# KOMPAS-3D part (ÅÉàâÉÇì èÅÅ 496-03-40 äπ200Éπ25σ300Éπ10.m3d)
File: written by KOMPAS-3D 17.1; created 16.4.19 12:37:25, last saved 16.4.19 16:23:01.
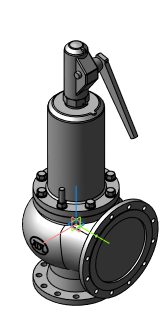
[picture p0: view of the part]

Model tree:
1. Операция без истории:12  (labels: Сталь 20  ГОСТ 1050-2013)

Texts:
  Линейный размер с обрывом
